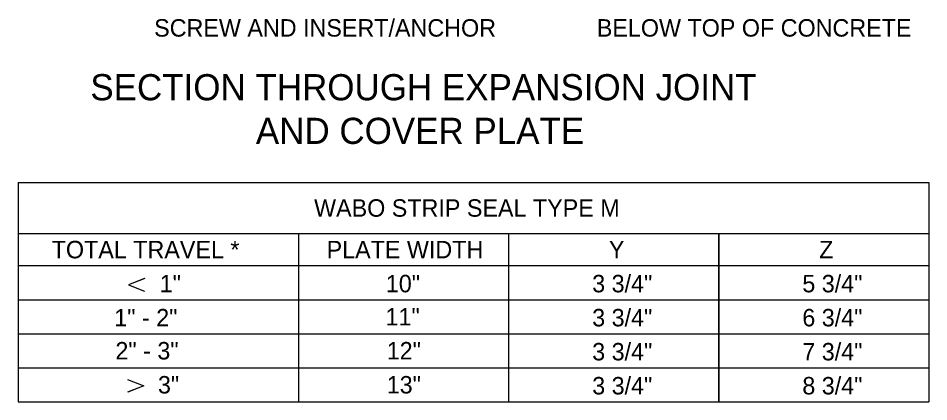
# Model space of a CAD drawing. Extents: x 19590 to 20151, y 19944 to 20103.
# Drawn here: x 19880.96 to 19906.96, y 20050.32 to 20061.26 of the extents above; entities that cross this region are included whole.
import ezdxf

# ---------------------------------------------------------------- set-up
doc = ezdxf.new("R2010")
doc.units = 0
for name, color, linetype in [('DETAIL_TEXT_DIMEN_PR', 7, 'Continuous'), ('Level 1', 7, 'Continuous'), ('MT_PAVT_MRKGS_EX_REF', 7, 'Continuous'), ('PAVT_MRKGS_QUANT', 7, 'Continuous')]:
    doc.layers.add(name, color=color, linetype=linetype)

# ---------------------------------------------------------------- blocks, each defined once
blk = doc.blocks.new('TERM')
at = {"layer": 'DETAIL_TEXT_DIMEN_PR'}
for p, q in [((-0.0388, -0.01), (0, 0)), ((0, 0), (-0.0387, 0.01))]:
    blk.add_line(p, q, dxfattribs=at)
blk = doc.blocks.new('EJ3H')
at = {"layer": 'MT_PAVT_MRKGS_EX_REF'}
for p, q in [((69.331, -39.53), (95.331, -39.53)), ((69.331, -39.53), (69.331, -45.787)), ((95.331, -39.53), (95.331, -45.787)), ((69.34, -40.987), (95.331, -40.987)), ((77.331, -40.987), (77.331, -45.787)), ((83.331, -40.987), (83.331, -45.787)), ((89.331, -40.987), (89.331, -45.787)), ((69.331, -41.904), (95.331, -41.904)), ((69.331, -42.875), (95.331, -42.875)), ((69.331, -43.846), (95.331, -43.846)), ((69.331, -44.817), (95.331, -44.817)), ((69.331, -45.787), (95.331, -45.787))]:
    blk.add_line(p, q, dxfattribs=at)
at = {"layer": 'PAVT_MRKGS_QUANT', "xscale": 12, "yscale": 18, "rotation": 180}
blk.add_blockref('TERM', (72.476, -42.451), dxfattribs=at)
at = {"layer": 'PAVT_MRKGS_QUANT', "xscale": 12, "yscale": -18}
blk.add_blockref('TERM', (72.921, -45.336), dxfattribs=at)
at = {"layer": 'MT_PAVT_MRKGS_EX_REF'}
for s, height, p in [('SCREW AND INSERT/ANCHOR', 0.49762, (73.213, -35.37)), ('BELOW TOP OF CONCRETE', 0.49762, (85.853, -35.37)), ('SECTION THROUGH EXPANSION JOINT', 0.74653, (71.391, -37.187)), ('AND COVER PLATE', 0.74653, (76.118, -38.431))]:
    blk.add_text(s, height=height, dxfattribs=at).set_placement(p)
for s, height, p in [('WABO STRIP SEAL TYPE M', 0.49762, (77.78, -40.508)), ('TOTAL TRAVEL *', 0.49762, (70.287, -41.695)), ('PLATE WIDTH', 0.49762, (78.137, -41.695)), ('Y', 0.498, (86.197, -41.695)), ('Z', 0.498, (92.201, -41.695)), (' 1"', 0.4976, (73.187, -42.665)), ('10"', 0.4976, (79.829, -42.665)), ('3 3/4"', 0.4976, (85.721, -42.665)), ('5 3/4"', 0.4976, (91.721, -42.665)), ('1" - 2"', 0.4976, (72.074, -43.636)), ('11"', 0.4976, (79.821, -43.609)), ('3 3/4"', 0.4976, (85.721, -43.636)), ('6 3/4"', 0.4976, (91.721, -43.636)), ('2" - 3"', 0.4976, (72.107, -44.58)), ('12"', 0.4976, (79.854, -44.58)), ('3 3/4"', 0.4976, (85.721, -44.607)), ('7 3/4"', 0.4976, (91.721, -44.607)), (' 3"', 0.4976, (73.136, -45.551)), ('13"', 0.4976, (79.854, -45.551)), ('3 3/4"', 0.4976, (85.721, -45.578)), ('8 3/4"', 0.4976, (91.721, -45.578))]:
    blk.add_text(s, height=height, rotation=0, dxfattribs=at).set_placement(p)

msp = doc.modelspace()

# ---------------------------------------------------------------- linework, layer by layer
at = {"layer": 'MT_PAVT_MRKGS_EX_REF'}
for p, q in [((19880.956, 20056.576), (19906.956, 20056.576)), ((19880.956, 20056.576), (19880.956, 20050.319)), ((19906.956, 20056.576), (19906.956, 20050.319)), ((19880.965, 20055.119), (19906.956, 20055.119)), ((19888.956, 20055.119), (19888.956, 20050.319)), ((19894.956, 20055.119), (19894.956, 20050.319)), ((19900.956, 20055.119), (19900.956, 20050.319)), ((19880.956, 20054.202), (19906.956, 20054.202)), ((19880.956, 20053.231), (19906.956, 20053.231)), ((19880.956, 20052.26), (19906.956, 20052.26)), ((19880.956, 20051.289), (19906.956, 20051.289)), ((19880.956, 20050.319), (19906.956, 20050.319))]:
    msp.add_line(p, q, dxfattribs=at)

# ---------------------------------------------------------------- block references
at = {"layer": 'Level 1'}
msp.add_blockref('EJ3H', (19811.624, 20096.106), dxfattribs=at)
at = {"layer": 'PAVT_MRKGS_QUANT', "xscale": 12, "yscale": 18, "rotation": 180}
msp.add_blockref('TERM', (19884.101, 20053.655), dxfattribs=at)
at = {"layer": 'PAVT_MRKGS_QUANT', "xscale": 12, "yscale": -18}
msp.add_blockref('TERM', (19884.546, 20050.77), dxfattribs=at)

# ---------------------------------------------------------------- texts
at = {"layer": 'MT_PAVT_MRKGS_EX_REF'}
for s, height, p in [('SCREW AND INSERT/ANCHOR', 0.49762, (19884.838, 20060.737)), ('BELOW TOP OF CONCRETE', 0.49762, (19897.477, 20060.737)), ('SECTION THROUGH EXPANSION JOINT', 0.74653, (19883.015, 20058.919)), ('AND COVER PLATE', 0.74653, (19887.742, 20057.675))]:
    msp.add_text(s, height=height, dxfattribs=at).set_placement(p)
for s, height, p in [('WABO STRIP SEAL TYPE M', 0.49762, (19889.404, 20055.598)), ('TOTAL TRAVEL *', 0.49762, (19881.912, 20054.412)), ('PLATE WIDTH', 0.49762, (19889.762, 20054.412)), ('Y', 0.498, (19897.822, 20054.412)), ('Z', 0.498, (19903.825, 20054.412)), (' 1"', 0.4976, (19884.811, 20053.441)), ('10"', 0.4976, (19891.453, 20053.441)), ('3 3/4"', 0.4976, (19897.345, 20053.441)), ('5 3/4"', 0.4976, (19903.345, 20053.441)), ('1" - 2"', 0.4976, (19883.699, 20052.47)), ('11"', 0.4976, (19891.445, 20052.497)), ('3 3/4"', 0.4976, (19897.345, 20052.47)), ('6 3/4"', 0.4976, (19903.345, 20052.47)), ('2" - 3"', 0.4976, (19883.731, 20051.526)), ('12"', 0.4976, (19891.478, 20051.526)), ('3 3/4"', 0.4976, (19897.345, 20051.499)), ('7 3/4"', 0.4976, (19903.345, 20051.499)), (' 3"', 0.4976, (19884.761, 20050.555)), ('13"', 0.4976, (19891.478, 20050.555)), ('3 3/4"', 0.4976, (19897.345, 20050.528)), ('8 3/4"', 0.4976, (19903.345, 20050.528))]:
    msp.add_text(s, height=height, rotation=0, dxfattribs=at).set_placement(p)

doc.saveas('drawing.dxf')
